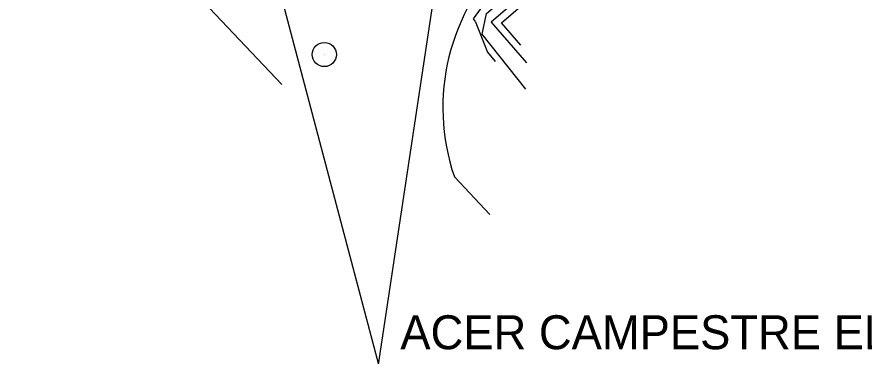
# Model space of a CAD drawing. Extents: x -438233 to -437334, y -1133133 to -1132623.
# Drawn here: x -438101.34 to -438066.2, y -1133036.13 to -1133022.09 of the extents above; entities that cross this region are included whole.
import ezdxf

# ---------------------------------------------------------------- set-up
doc = ezdxf.new("R2010")
doc.units = 0
for name, color, linetype in [('Vrstva 1', 7, 'Continuous'), ('Vrstva 11', 7, 'Continuous'), ('Vrstva 27', 7, 'Continuous'), ('Vrstva 40', 7, 'Continuous'), ('Vrstva 53', 7, 'Continuous'), ('Vrstva 7', 7, 'Continuous')]:
    doc.layers.add(name, color=color, linetype=linetype)

msp = doc.modelspace()

# ---------------------------------------------------------------- linework, layer by layer
at = {"layer": 'Vrstva 1'}
for p, q in [((-438081.667, -1133022.306), (-438081.667, -1133022.306)), ((-438083.274, -1133023.222), (-438083.274, -1133023.222)), ((-438088.59, -1133023.649), (-438088.59, -1133023.649)), ((-438088.583, -1133023.638), (-438088.583, -1133023.638))]:
    msp.add_line(p, q, dxfattribs=at)
at = {"layer": 'Vrstva 11'}
for points in [[(-438090.347, -1133024.892), (-438094.859, -1133020.125), (-438101.339, -1133013.202)], [(-438083.197, -1133028.711), (-438081.721, -1133030.27)]]:
    msp.add_lwpolyline(points, dxfattribs=at)
msp.add_arc((-438074.85, -1133025.849), 8.824, 133.5251, 198.9272, dxfattribs=at)
at = {"layer": 'Vrstva 27'}
msp.add_circle((-438088.59, -1133023.649), 0.5, dxfattribs=at)
at = {"layer": 'Vrstva 40'}
msp.add_line((-438086.346, -1133036.484), (-438082.516, -1133011.089), dxfattribs=at)
msp.add_lwpolyline([(-438093.636, -1133008.975), (-438086.346, -1133036.484), (-438083.989, -1133036.484)], dxfattribs=at)
at = {"layer": 'Vrstva 53'}
for points in [[(-438082.34, -1133022.27), (-438082.4, -1133022.17), (-438081.23, -1133020.54), (-438076.87, -1133017.08), (-438069.83, -1133010.55), (-438064.49, -1133005.53), (-438059.58, -1133001.78), (-438053.45, -1132996.74), (-438044, -1132988.47), (-438035.57, -1132981.06), (-438029.47, -1132975.65), (-438020.01, -1132967.31), (-438013.46, -1132961.68), (-438012.29, -1132959.83), (-438009.79, -1132957.66), (-438009.76, -1132957.6), (-438007.47, -1132956.33), (-438007.65, -1132955.49), (-438008.56, -1132952.65)], [(-438080.228, -1133025.09), (-438082.04, -1133022.81), (-438081.87, -1133021.95), (-438073.76, -1133015.09), (-438028.25, -1132974.2), (-438011.87, -1132960.69), (-438014.77, -1132957.4)], [(-438082.34, -1133022.27), (-438081.82, -1133023.55), (-438081.505, -1133023.931)]]:
    msp.add_lwpolyline(points, dxfattribs=at)
at = {"layer": 'Vrstva 7'}
for points in [[(-438076.048, -1133017.473), (-438081.667, -1133022.306), (-438080.202, -1133023.989)], [(-438080.435, -1133023.265), (-438081.243, -1133022.337), (-438075.852, -1133017.7)]]:
    msp.add_lwpolyline(points, dxfattribs=at)

# ---------------------------------------------------------------- texts
at = {"layer": 'Vrstva 1'}
msp.add_text('ACER CAMPESTRE ELEGANT - 2 ks', height=1.40625, dxfattribs=at).set_placement((-438085.438, -1133035.851))

doc.saveas('drawing.dxf')
